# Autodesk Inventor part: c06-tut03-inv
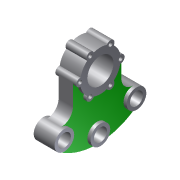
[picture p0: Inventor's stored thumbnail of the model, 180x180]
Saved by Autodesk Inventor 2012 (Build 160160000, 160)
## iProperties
Created: 2010-03
Part Number: c06-tut03-inv
Document SubType Name: Modeling
Designer: CADSoft
Density: 1 g/cm^3
Material: Default
Author: CADSoft
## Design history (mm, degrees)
sketch "Sketch1"
  geometry: 1 further point
sketch "Sketch2"
  geometry: L1 (-37, 0)-(-37, -31.635); L2 (37, 0)-(37, -31.635); A1 r 100 centre (0, 0) between (-64.945, -76.041) and (64.945, -76.041); A2 r 18 centre (-55, -31.635) between (-55.111, -49.635) and (-37, -31.635); A3 r 15 centre (-55.203, -64.635) between (-55.111, -49.635) and (-64.945, -76.041); A4 r 18 centre (55, -31.635) between (37, -31.635) and (55.111, -49.635); A5 r 15 centre (55.203, -64.635) between (64.945, -76.041) and (55.111, -49.635); A6 r 31 centre (0, 0) between (30.419, 5.972) and (-30.419, 5.972); A7 r 6 centre (31, 0) between (37, 0) and (30.419, 5.972); A8 r 6 centre (-31, 0) between (-30.419, 5.972) and (-37, 0); 1 further point
  constraints: 18 point on circle, 8 centre point, 8 tangent, 4 end point, 3 equal radius, 2 coincident, 2 horizontal alignment, 2 vertical, 1 parallel, 1 point on line
  dimensions: "d0" = 100 radius of A1; "d4" = 15 radius of A5; "d5" = 18 radius of A4; "d7" = 81 deg dimension on point (0, 0) A5.centre A3.centre; "d16" = 31 radius of A6; "d17" = 6 radius of A8
extrude "Extrusion1" new body sketch "Sketch2" stored distance "d8" = 22; taper "d9" = 0 deg
sketch "Sketch5"
  geometry: A1 r 6 centre (-31, 0) between (-30.419, 5.972) and (-30.419, -5.972); A2 r 6 centre (-31, 0) between (-30.419, 5.972) and (-37, 0) reference; A3 r 6 centre (-15.5, -26.847) between (-20.381, -23.358) and (-10.038, -29.33); A4 r 6 centre (15.5, -26.847) between (10.038, -29.33) and (20.381, -23.358); A5 r 6 centre (31, 0) between (30.419, -5.972) and (30.419, 5.972); A6 r 6 centre (15.5, 26.847) between (20.381, 23.358) and (10.038, 29.33); A7 r 6 centre (-15.5, 26.847) between (-10.038, 29.33) and (-20.381, 23.358); A8 r 31 centre (0, 0) between (10.038, 29.33) and (-10.038, 29.33); A9 r 31 centre (0, 0) between (30.419, 5.972) and (20.381, 23.358); A10 r 31 centre (0, 0) between (20.381, -23.358) and (30.419, -5.972); A11 r 31 centre (0, 0) between (-20.381, 23.358) and (-30.419, 5.972); A12 r 31 centre (0, 0) between (-30.419, -5.972) and (-20.381, -23.358); A13 r 31 centre (0, 0) between (-10.038, -29.33) and (10.038, -29.33); 1 further point
  constraints: 26 point on circle, 12 centre point, 1 coincident, 1 concentric
extrude "Extrusion2" join sketch "Sketch5" stored distance "d19" = 32; taper "d20" = 0 deg
hole "Hole1" diameter "d23" = 6; stored, may be unused: countersink angle "d27" = 90 deg, drill point angle "d29" = 118 deg; dims "d21" = 10, "d22" = 10, "d24" = 6, "d25" = 4, "d26" = 2, "d28" = 8
pattern_circular "Circular Pattern1" dims angle "d31" = 360 deg
sketch "Sketch6"
  geometry: C1 r 15 at (-55.203, -64.635); A1 r 15 centre (-55.203, -64.635) between (-55.111, -49.635) and (-64.945, -76.041) reference; 1 further point
  constraints: 1 centre point, 1 concentric
  dimensions: "d33" = 30 diameter of C1
extrude "Extrusion3" join sketch "Sketch6" stored distance "d34" = 32; taper "d35" = 0 deg
hole "Hole2" diameter "d38" = 20; stored, may be unused: countersink angle "d42" = 90 deg, drill point angle "d44" = 118 deg; dims "d36" = 10, "d37" = 10, "d39" = 6, "d40" = 4, "d41" = 2, "d43" = 8
pattern_circular "Circular Pattern2" dims angle "d46" = 81 deg
hole "Hole3" diameter "d50" = 40; stored, may be unused: countersink angle "d54" = 90 deg, drill point angle "d56" = 118 deg; dims "d48" = 10, "d49" = 10, "d51" = 6, "d52" = 4, "d53" = 2, "d55" = 8
body "Solid1"
other parameters: "d18" = 62
